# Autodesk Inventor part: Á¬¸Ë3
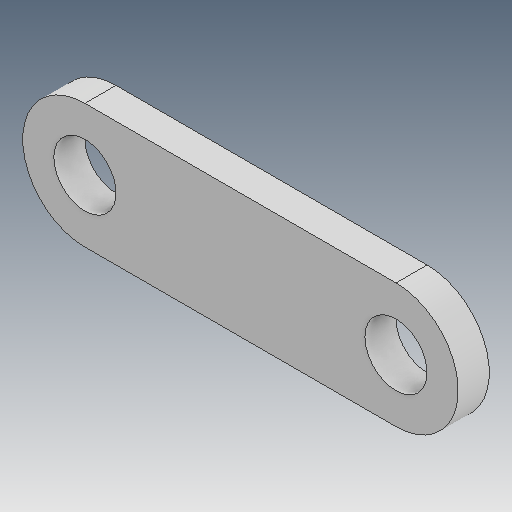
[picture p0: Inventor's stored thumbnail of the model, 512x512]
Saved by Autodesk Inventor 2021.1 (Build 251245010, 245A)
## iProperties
Created: 2013-04
Part Number: Á¬¸Ë3
Material: Ogólny
Document SubType Name: Modeling
Designer: user
Density: 1 g/cm^3
Appearance: Domyślna
Author: user
Revision Number: ÈÎºÎ
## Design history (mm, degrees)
feature "À­Éì1"
node "Bryła1"
